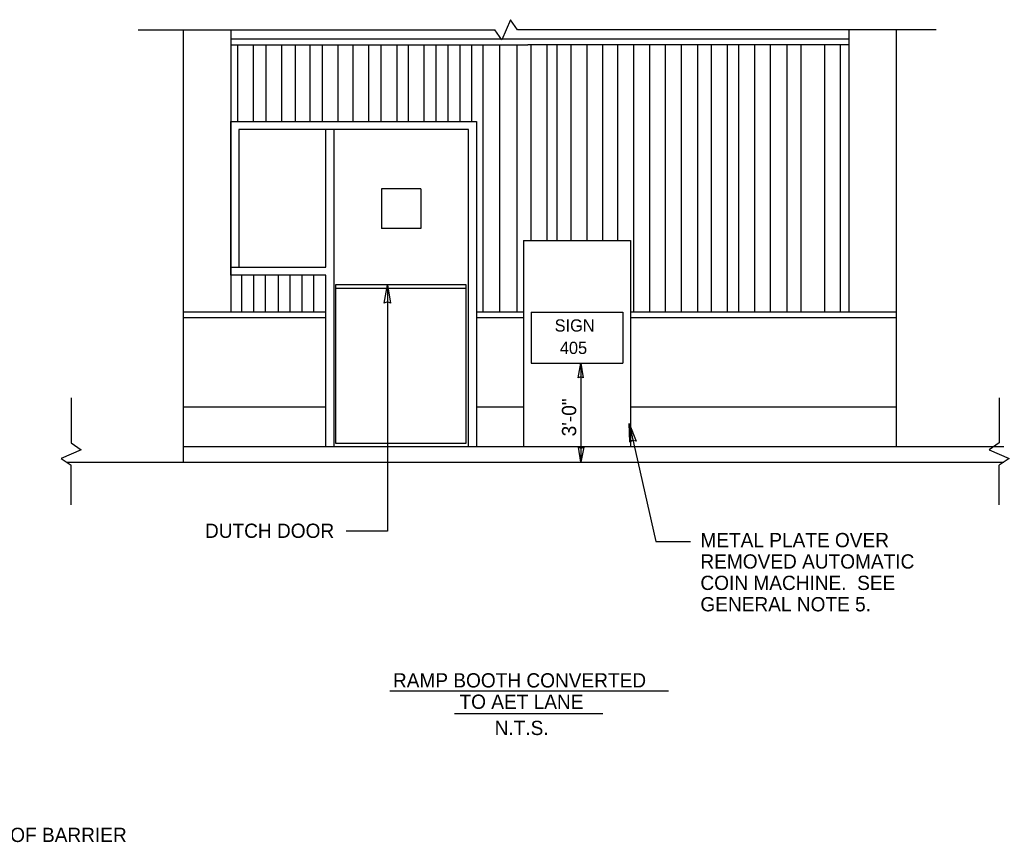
# Model space of a CAD drawing. Extents: x -63400 to -62632, y -1624834 to -1624417.
# Drawn here: x -62962.7 to -62768.4, y -1624578.5 to -1624417 of the extents above; entities that cross this region are included whole.
import ezdxf

# ---------------------------------------------------------------- set-up
doc = ezdxf.new("R2010")
doc.units = 0
for name, color, linetype in [('15', 7, 'Continuous'), ('21', 7, 'Continuous'), ('33', 7, 'Continuous'), ('52', 7, 'Continuous'), ('6', 7, 'Continuous'), ('LeaderLine_dp', 7, 'Continuous'), ('SignPanel', 7, 'Continuous'), ('TextDetails', 7, 'Continuous'), ('TextLabel', 7, 'Continuous')]:
    doc.layers.add(name, color=color, linetype=linetype)

# ---------------------------------------------------------------- blocks, each defined once
blk = doc.blocks.new('T52')
at = {"layer": '52'}
blk.add_lwpolyline([(0, 0), (-0.146, -0.023), (-0.135, 0.002), (-0.145, 0.028)], close=True, dxfattribs=at)
blk = doc.blocks.new('BREAK2')
at = {"layer": '21'}
for p, q in [((0.283, 0.654), (-0.283, -0.653)), ((0.738, 0), (0.283, 0.654)), ((-3.324, 0), (-0.737, 0)), ((-0.283, -0.653), (-0.737, 0)), ((3.67, 0), (0.738, 0))]:
    blk.add_line(p, q, dxfattribs=at)

msp = doc.modelspace()

# ---------------------------------------------------------------- linework, layer by layer
at = {"layer": '15'}
for p, q in [((-62919.91, -1624436.98), (-62919.91, -1624421.9)), ((-62916.81, -1624436.98), (-62916.81, -1624421.9)), ((-62914.37, -1624436.98), (-62914.37, -1624421.9)), ((-62911.26, -1624436.98), (-62911.26, -1624421.9)), ((-62908.56, -1624436.98), (-62908.56, -1624421.9)), ((-62905.72, -1624436.98), (-62905.72, -1624421.9)), ((-62903.29, -1624436.98), (-62903.29, -1624421.9)), ((-62900.17, -1624436.98), (-62900.17, -1624421.9)), ((-62897.28, -1624436.98), (-62897.28, -1624421.9)), ((-62894.16, -1624436.98), (-62894.16, -1624421.9)), ((-62891.73, -1624436.98), (-62891.73, -1624421.9)), ((-62888.62, -1624436.98), (-62888.62, -1624421.9)), ((-62886.39, -1624436.98), (-62886.39, -1624421.9)), ((-62883.28, -1624436.98), (-62883.28, -1624421.9)), ((-62880.94, -1624436.98), (-62880.94, -1624421.9)), ((-62878.6, -1624436.98), (-62878.6, -1624421.9)), ((-62876.27, -1624436.98), (-62876.27, -1624421.9)), ((-62873.93, -1624436.98), (-62873.93, -1624421.9)), ((-62871.7, -1624474.43), (-62871.7, -1624421.9)), ((-62868.46, -1624474.43), (-62868.46, -1624421.9)), ((-62865.04, -1624474.43), (-62865.04, -1624421.9)), ((-62862.28, -1624460.32), (-62862.28, -1624421.9)), ((-62859.16, -1624460.32), (-62859.16, -1624421.9)), ((-62857.19, -1624460.32), (-62857.19, -1624421.9)), ((-62854.41, -1624460.32), (-62854.41, -1624421.9)), ((-62851.31, -1624460.32), (-62851.31, -1624421.9)), ((-62848.2, -1624460.32), (-62848.2, -1624421.9)), ((-62845.25, -1624460.32), (-62845.25, -1624421.9)), ((-62842.11, -1624474.43), (-62842.11, -1624421.9)), ((-62839.01, -1624474.43), (-62839.01, -1624421.9)), ((-62835.89, -1624474.43), (-62835.89, -1624421.9)), ((-62832.78, -1624474.43), (-62832.78, -1624421.9)), ((-62829.54, -1624474.43), (-62829.54, -1624421.9)), ((-62826.86, -1624474.43), (-62826.86, -1624421.9)), ((-62823.76, -1624474.43), (-62823.76, -1624421.9)), ((-62821.5, -1624474.43), (-62821.5, -1624421.9)), ((-62818.39, -1624474.43), (-62818.39, -1624421.9)), ((-62815.27, -1624474.43), (-62815.27, -1624421.9)), ((-62812.04, -1624474.43), (-62812.04, -1624421.9)), ((-62809.29, -1624474.43), (-62809.29, -1624421.9)), ((-62804.63, -1624474.43), (-62804.63, -1624421.9)), ((-62801.51, -1624474.43), (-62801.51, -1624421.9)), ((-62919.11, -1624474.43), (-62919.11, -1624467.13)), ((-62916.78, -1624474.43), (-62916.78, -1624467.13)), ((-62914.45, -1624474.43), (-62914.45, -1624467.13)), ((-62911.95, -1624474.43), (-62911.95, -1624467.13)), ((-62909.62, -1624474.43), (-62909.62, -1624467.13)), ((-62907.28, -1624474.43), (-62907.28, -1624467.13)), ((-62905.01, -1624474.43), (-62905.01, -1624467.13))]:
    msp.add_line(p, q, dxfattribs=at)
at = {"layer": '21'}
for p, q in [((-62866.36, -1624417), (-62868.06, -1624420.92)), ((-62864.99, -1624418.96), (-62866.36, -1624417)), ((-62939.49, -1624418.96), (-62869.42, -1624418.96)), ((-62868.06, -1624420.92), (-62869.42, -1624418.96)), ((-62782.74, -1624418.96), (-62864.99, -1624418.96))]:
    msp.add_line(p, q, dxfattribs=at)
at = {"layer": '33'}
for p, q in [((-62930.62, -1624418.96), (-62930.62, -1624503.86)), ((-62921.29, -1624418.96), (-62921.29, -1624474.43)), ((-62799.91, -1624418.96), (-62799.91, -1624474.43)), ((-62790.58, -1624418.96), (-62790.58, -1624500.78)), ((-62921.29, -1624420.77), (-62799.91, -1624420.77)), ((-62921.29, -1624421.9), (-62862.95, -1624421.9)), ((-62799.91, -1624421.9), (-62862.95, -1624421.9)), ((-62883.94, -1624450.21), (-62891.71, -1624450.21)), ((-62891.71, -1624450.21), (-62891.71, -1624457.99)), ((-62883.94, -1624450.21), (-62883.94, -1624457.99)), ((-62883.94, -1624457.99), (-62891.71, -1624457.99)), ((-62863.77, -1624460.32), (-62842.77, -1624460.32)), ((-62875.07, -1624469.04), (-62900.7, -1624469.04)), ((-62900.7, -1624469.04), (-62900.7, -1624500.16)), ((-62875.07, -1624500.16), (-62875.07, -1624469.04)), ((-62875.07, -1624469.81), (-62900.7, -1624469.81)), ((-62902.61, -1624474.43), (-62930.62, -1624474.43)), ((-62902.61, -1624475.55), (-62930.62, -1624475.55)), ((-62863.77, -1624474.43), (-62873.05, -1624474.43)), ((-62863.77, -1624475.55), (-62873.05, -1624475.55)), ((-62819.03, -1624474.43), (-62842.77, -1624474.43)), ((-62819.03, -1624475.55), (-62842.77, -1624475.55)), ((-62790.58, -1624474.43), (-62819.03, -1624474.43)), ((-62790.58, -1624475.55), (-62819.03, -1624475.55)), ((-62930.62, -1624493), (-62902.61, -1624493)), ((-62873.05, -1624493), (-62863.77, -1624493)), ((-62842.77, -1624493), (-62819.03, -1624493)), ((-62819.03, -1624493), (-62790.58, -1624493)), ((-62930.62, -1624500.78), (-62769.44, -1624500.78)), ((-62900.7, -1624500.16), (-62875.07, -1624500.16)), ((-62953.59, -1624503.86), (-62769.44, -1624503.86))]:
    msp.add_line(p, q, dxfattribs=at)
at = {"layer": '6'}
for p, q in [((-62921.29, -1624436.98), (-62873.05, -1624436.98)), ((-62921.29, -1624467.13), (-62921.29, -1624436.98)), ((-62901.05, -1624438.53), (-62919.73, -1624438.53)), ((-62919.73, -1624438.53), (-62919.73, -1624465.57)), ((-62902.61, -1624465.57), (-62902.61, -1624438.53)), ((-62901.05, -1624438.53), (-62901.05, -1624500.78)), ((-62874.6, -1624438.53), (-62901.05, -1624438.53)), ((-62901.05, -1624438.53), (-62901.05, -1624438.53)), ((-62874.6, -1624500.78), (-62874.6, -1624438.53)), ((-62873.05, -1624436.98), (-62873.05, -1624500.78)), ((-62863.77, -1624460.32), (-62863.77, -1624500.78)), ((-62842.77, -1624460.32), (-62842.77, -1624500.78)), ((-62921.29, -1624465.57), (-62902.61, -1624465.57)), ((-62902.61, -1624467.13), (-62921.29, -1624467.13)), ((-62902.61, -1624500.78), (-62902.61, -1624467.13))]:
    msp.add_line(p, q, dxfattribs=at)
at = {"layer": 'LeaderLine_dp'}
for p, q in [((-62890.48, -1624469.04), (-62890.48, -1624517.41)), ((-62852.51, -1624484.43), (-62852.51, -1624503.86)), ((-62843.06, -1624496.3), (-62837.82, -1624519.5)), ((-62890.48, -1624517.41), (-62898.61, -1624517.41)), ((-62837.82, -1624519.5), (-62831.01, -1624519.5))]:
    msp.add_line(p, q, dxfattribs=at)
at = {"layer": 'SignPanel'}
for p, q in [((-62862.28, -1624474.43), (-62844.27, -1624474.43)), ((-62862.27, -1624474.43), (-62862.27, -1624484.43)), ((-62844.27, -1624474.43), (-62844.27, -1624484.43)), ((-62862.28, -1624484.43), (-62844.27, -1624484.43))]:
    msp.add_line(p, q, dxfattribs=at)
at = {"layer": 'TextDetails'}
for p, q in [((-62890.08, -1624548.81), (-62835.35, -1624548.81)), ((-62877.37, -1624553.27), (-62848.21, -1624553.27))]:
    msp.add_line(p, q, dxfattribs=at)

# ---------------------------------------------------------------- block references
at = {"layer": '21', "xscale": 3}
for p, yscale, rotation in [((-62952.67, -1624502.29), -3, 90.00000000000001), ((-62770.36, -1624502.29), 3, 90)]:
    msp.add_blockref('BREAK2', p, dxfattribs=dict(at, yscale=yscale, rotation=rotation))
at = {"layer": 'LeaderLine_dp'}
for p, xscale, yscale, rotation in [((-62890.48, -1624469.04), 25, 25, 90), ((-62852.51, -1624484.43), 20, 20, 90), ((-62843.06, -1624496.3), 25, 25.000000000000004, 102.73283702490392), ((-62852.51, -1624503.86), 20, 20, -90)]:
    msp.add_blockref('T52', p, dxfattribs=dict(at, xscale=xscale, yscale=yscale, rotation=rotation))

# ---------------------------------------------------------------- texts
at = {"layer": 'SignPanel'}
for s, p in [('SIGN', (-62857.68, -1624478.24)), ('405', (-62856.66, -1624482.64))]:
    msp.add_text(s, height=2.4, dxfattribs=at).set_placement(p)
at = {"layer": 'TextDetails'}
for s, p in [('RAMP BOOTH CONVERTED', (-62889.44, -1624548.14)), ('TO AET LANE', (-62876.37, -1624552.34)), ('N.T.S.', (-62869.47, -1624557.48))]:
    msp.add_text(s, height=2.8, dxfattribs=at).set_placement(p)
at = {"layer": 'TextLabel'}
msp.add_text('3\'-0"', height=2.8, rotation=90, dxfattribs=at).set_placement((-62853.45, -1624498.82))
for s, p in [('DUTCH DOOR', (-62926.36, -1624518.76)), ('METAL PLATE OVER', (-62829.05, -1624520.59)), ('REMOVED AUTOMATIC', (-62829.05, -1624524.79)), ('COIN MACHINE.  SEE', (-62829.05, -1624528.99)), ('GENERAL NOTE 5.', (-62829.05, -1624533.19)), ('TOP OF BARRIER', (-62973.35, -1624578.49))]:
    msp.add_text(s, height=2.8, dxfattribs=at).set_placement(p)

doc.saveas('drawing.dxf')
